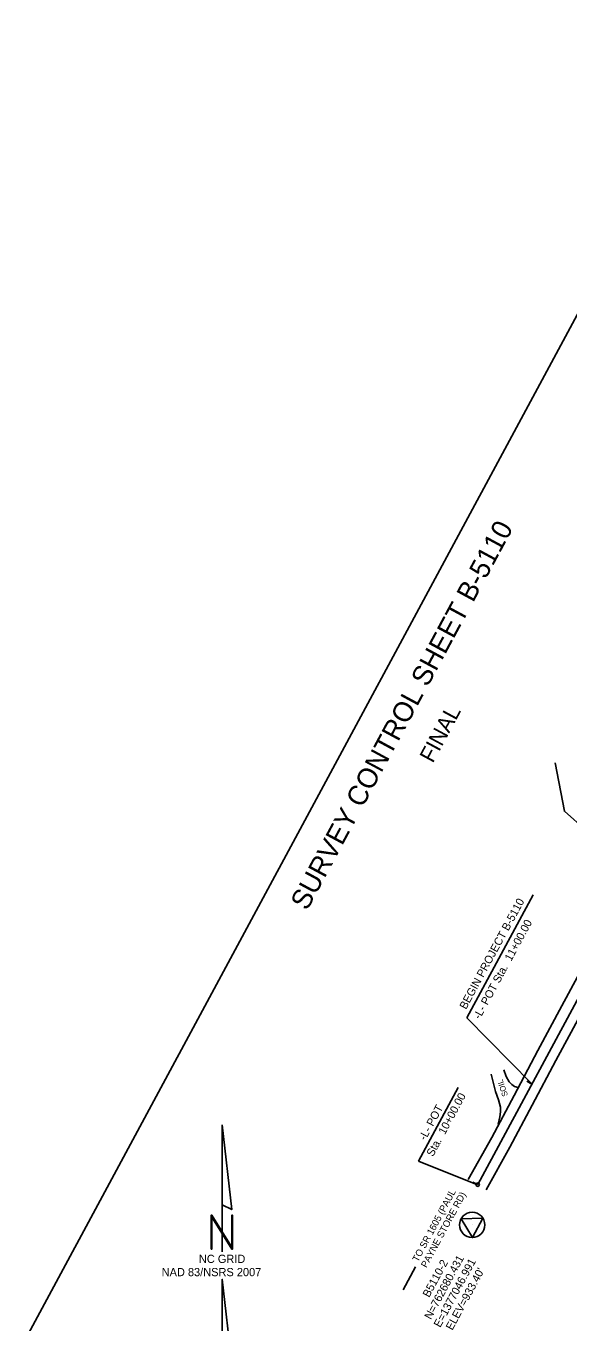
# Model space of a CAD drawing. Extents: x 1376594 to 1378079, y 762010 to 763753.
# Drawn here: x 1376656 to 1377131, y 762595 to 763729 of the extents above; entities that cross this region are included whole.
import ezdxf

# ---------------------------------------------------------------- set-up
doc = ezdxf.new("R2010")
doc.units = 0
for name, color, linetype in [('CTL GPS Vertical Text', 7, 'Continuous'), ('CTL NGS Horizontal and Vertical CELL', 7, 'Continuous'), ('CTL North Arrow NAD 83 NSRS 2007 CELL', 7, 'Continuous'), ('CTL Sheet Border CELL', 7, 'Continuous'), ('Default', 7, 'Continuous'), ('Exist Hydro Stream or Body of Water', 7, 'Continuous'), ('Exist Roads EOP', 7, 'Continuous'), ('Exist Roads EOP Leader', 7, 'Continuous'), ('Exist Roads EOP Text', 7, 'Continuous'), ('Exist Roads Soil', 7, 'Continuous'), ('Exist Roads Soil Text', 7, 'Continuous'), ('Prop Horizontal Alignment', 7, 'Continuous'), ('Prop Horizontal Alignment Station Label', 7, 'Continuous'), ('Prop Horizontal Alignment Tick Large', 7, 'Continuous'), ('Prop Horizontal Alignment Tick Small', 7, 'Continuous')]:
    doc.layers.add(name, color=color, linetype=linetype)

# ---------------------------------------------------------------- blocks, each defined once
blk = doc.blocks.new('CTL NORTH ARROW NAD 83 NSRS 2007')
at = {"layer": 'Default'}
blk.add_line((0, 0), (0, 0), dxfattribs=at)
for points in [[(-0.003, 1.746), (-0.003, 0.579), (0.135, 0.511)], [(-0.168, -0.065), (-0.154, -0.065), (-0.154, 0.401), (0.135, -0.065), (0.148, -0.065), (0.148, 0.428), (0.135, 0.428), (0.135, -0.038), (-0.154, 0.428), (-0.168, 0.428)], [(-0.003, -1.671), (0.135, -1.739), (-0.003, -0.505)]]:
    blk.add_lwpolyline(points, close=True, dxfattribs=at)
blk.add_lwpolyline([(-0.003, 0.579), (-0.003, -0.107)], dxfattribs=at)
for s, p in [('NC GRID', (-0.345, -0.267)), ('NAD 83/NSRS 2007', (-0.888, -0.46))]:
    blk.add_text(s, height=0.12, dxfattribs=at).set_placement(p)
blk = doc.blocks.new('CTL NGS HORIZONTAL AND VERTICAL')
at = {"layer": 'CTL NGS Horizontal and Vertical CELL'}
blk.add_line((0, 0), (0, 0), dxfattribs=at)
blk.add_lwpolyline([(-0.0638, -0.0372), (0.0638, -0.0372), (0, 0.0737)], close=True, dxfattribs=at)
blk.add_circle((0, -0.0001), 0.0738, dxfattribs=at)

msp = doc.modelspace()

# ---------------------------------------------------------------- linework, layer by layer
at = {"layer": 'CTL Sheet Border CELL'}
msp.add_lwpolyline([(1377275.2, 763729.2), (1376656.3, 762581.1), (1377459.9, 762147.8), (1378078.9, 763296)], close=True, dxfattribs=at)
at = {"layer": 'Default'}
for p, q in [((1377100.4, 762969.2), (1377042.4, 762861.6)), ((1377042.4, 762861.6), (1377099.2, 762803.7))]:
    msp.add_line(p, q, dxfattribs=at)
at = {"layer": 'Exist Hydro Stream or Body of Water'}
msp.add_lwpolyline([(1377202.4, 763025.9), (1377192, 763026.3), (1377157.5, 763022.2), (1377146.7, 763025.5), (1377127.7, 763042.2), (1377119.6, 763084.6)], dxfattribs=at)
at = {"layer": 'Exist Roads EOP'}
for points in [[(1377043.4, 762720.1), (1377064.1, 762756.8), (1377083.8, 762793.6), (1377104.6, 762833), (1377125.6, 762872.1), (1377147, 762912.1), (1377167, 762950.7), (1377187.4, 762988.4), (1377197.3, 763006.6)], [(1377059.3, 762711.2), (1377079.8, 762748.5), (1377099.4, 762785.1), (1377120.3, 762824.2), (1377141.4, 762863.7), (1377162.5, 762903.8), (1377182.7, 762942.3), (1377204.5, 762980.6), (1377213.9, 762997.7)]]:
    msp.add_lwpolyline(points, dxfattribs=at)
at = {"layer": 'Exist Roads EOP Leader'}
msp.add_lwpolyline([(1376986.6, 762623.5), (1376997.5, 762643.7)], dxfattribs=at)
at = {"layer": 'Exist Roads Soil'}
for points in [[(1377087.1, 762800.6), (1377083.9, 762801.6), (1377081.8, 762803.1), (1377079.5, 762805.5), (1377076.8, 762810.2), (1377074.7, 762815.9)], [(1377069.8, 762768.4), (1377071.3, 762774.8), (1377071.7, 762779.3), (1377071.7, 762783.3), (1377069.9, 762789.7), (1377067.5, 762797), (1377063.5, 762812.1)]]:
    msp.add_lwpolyline(points, dxfattribs=at)
at = {"layer": 'Prop Horizontal Alignment'}
msp.add_line((1377051.8, 762715.6), (1377431.4, 763419.8), dxfattribs=at)
at = {"layer": 'Prop Horizontal Alignment Station Label'}
for p in [(1377034.7, 762800.6), (1377050.3, 762715.9)]:
    msp.add_line(p, (1376999.9, 762736), dxfattribs=at)
msp.add_circle((1377051.8, 762715.6), 1.5, dxfattribs=at)
at = {"layer": 'Prop Horizontal Alignment Tick Large'}
msp.add_line((1377051.8, 762715.6), (1377047.5, 762717.9), dxfattribs=at)
at = {"layer": 'Prop Horizontal Alignment Tick Small'}
msp.add_line((1377099.3, 762803.6), (1377094.9, 762806), dxfattribs=at)

# ---------------------------------------------------------------- block references
at = {"layer": 'CTL NGS Horizontal and Vertical CELL', "xscale": 150, "yscale": 150, "rotation": -58.36276881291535}
msp.add_blockref('CTL NGS HORIZONTAL AND VERTICAL', (1377047, 762680.4), dxfattribs=at)
at = {"layer": 'CTL North Arrow NAD 83 NSRS 2007 CELL', "xscale": 60, "yscale": 60}
msp.add_blockref('CTL NORTH ARROW NAD 83 NSRS 2007', (1376828.4, 762663.1), dxfattribs=at)

# ---------------------------------------------------------------- texts
at = {"layer": 'CTL GPS Vertical Text'}
for s, p in [('B5110-2', (1377009.3, 762616.4)), ('N=762680.431', (1377010.8, 762597.1)), ('E=1377046.991', (1377019, 762590.1)), ("ELEV=933.40'", (1377029.6, 762587.7))]:
    msp.add_text(s, height=7, rotation=61.6702, dxfattribs=at).set_placement(p)
at = {"layer": 'CTL Sheet Border CELL'}
for s, height, p in [('SURVEY CONTROL SHEET B-5110', 17.391, (1376902.4, 762954.6)), ('FINAL', 13.91, (1377012.5, 763083.7))]:
    msp.add_text(s, height=height, rotation=61.6702, dxfattribs=at).set_placement(p)
at = {"layer": 'Default'}
for s, p in [('BEGIN PROJECT B-5110', (1377041.6, 762868.4)), ('-L- POT Sta.  11+00.00', (1377053.7, 762859.7))]:
    msp.add_text(s, height=7, rotation=61.6702, dxfattribs=at).set_placement(p)
at = {"layer": 'Exist Roads EOP Text'}
for s, p in [('TO SR 1605 (PAUL', (1376999.5, 762647.5)), ('PAYNE STORE RD)', (1377007, 762642.4))]:
    msp.add_text(s, height=6, rotation=61.718, dxfattribs=at).set_placement(p)
at = {"layer": 'Exist Roads Soil Text'}
msp.add_text('SOIL', height=5, rotation=108.6909, dxfattribs=at).set_placement((1377078.4, 762793.7))
at = {"layer": 'Prop Horizontal Alignment Station Label'}
for s, p in [('Sta.  10+00.00', (1377012.7, 762739.6)), ('-L- POT', (1377006, 762753.7))]:
    msp.add_text(s, height=7, rotation=61.6702, dxfattribs=at).set_placement(p)

doc.saveas('drawing.dxf')
